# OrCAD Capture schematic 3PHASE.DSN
size A
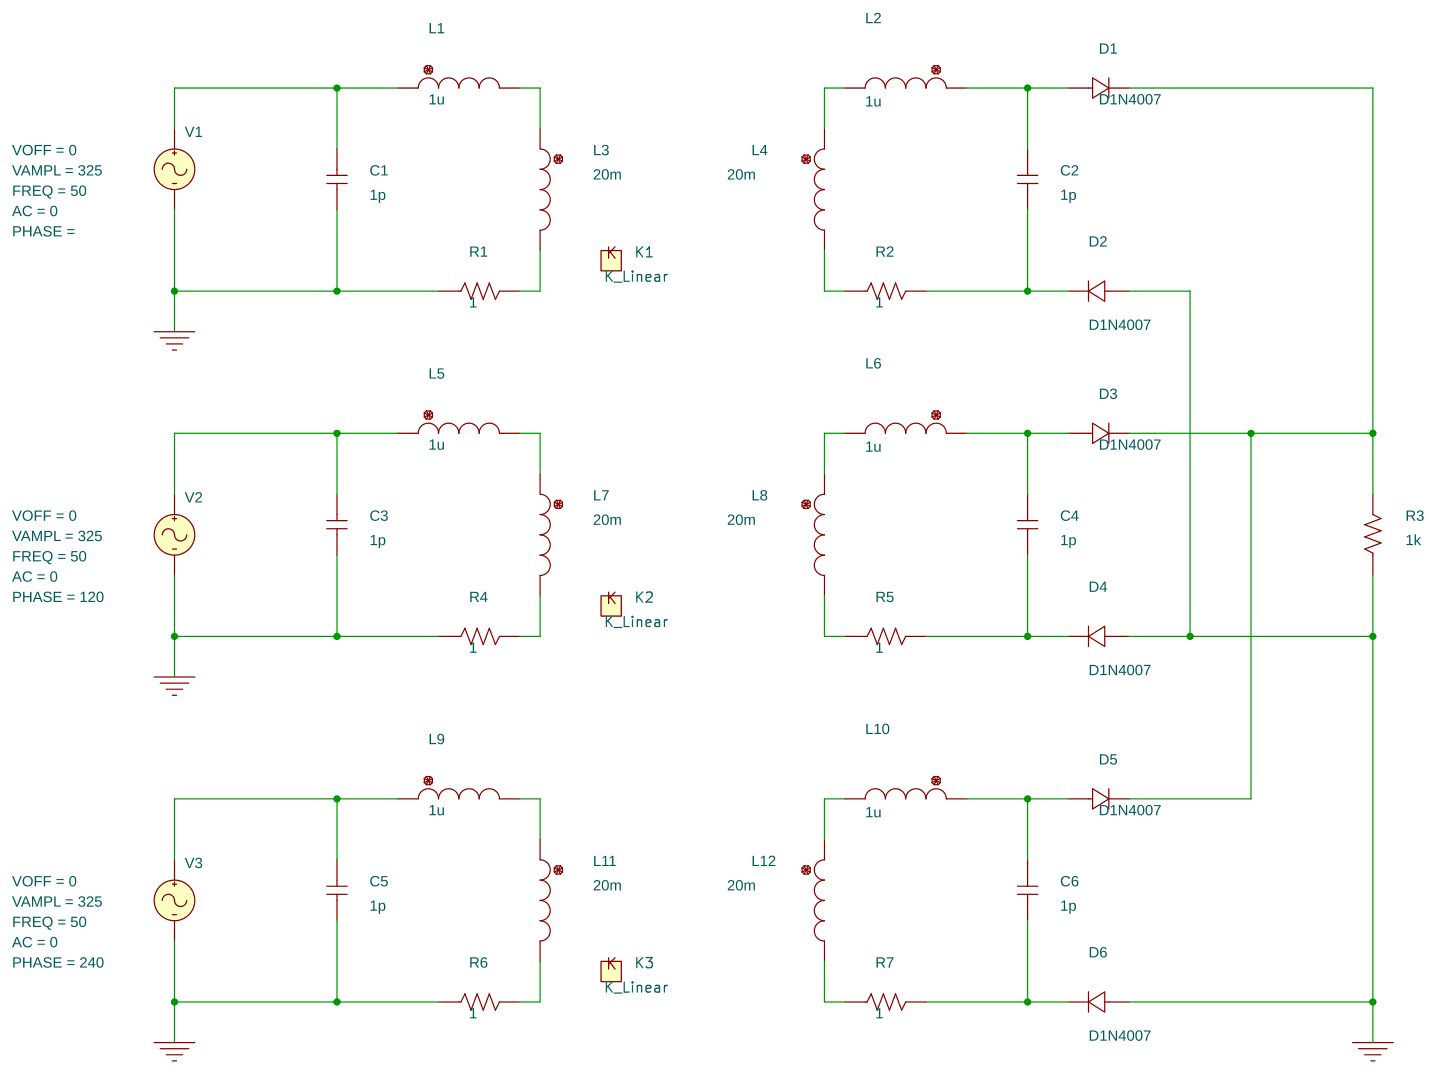
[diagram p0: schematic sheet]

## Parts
C1  1p  [RAD/CK05]
C2  1p  [RAD/CK05]
C3  1p  [RAD/CK05]
C4  1p  [RAD/CK05]
C5  1p  [RAD/CK05]
C6  1p  [RAD/CK05]
D1  D1N4007  [DO-41]
D2  D1N4007  [DO-41]
D3  D1N4007  [DO-41]
D4  D1N4007  [DO-41]
D5  D1N4007  [DO-41]
D6  D1N4007  [DO-41]
K1  K_Linear
K2  K_Linear
K3  K_Linear
L1  1u  [DISC/.350x.175/LS.200x.100/.034]
L2  1u  [DISC/.350x.175/LS.200x.100/.034]
L3  20m  [DISC/.350x.175/LS.200x.100/.034]
L4  20m  [DISC/.350x.175/LS.200x.100/.034]
L5  1u  [DISC/.350x.175/LS.200x.100/.034]
L6  1u  [DISC/.350x.175/LS.200x.100/.034]
L7  20m  [DISC/.350x.175/LS.200x.100/.034]
L8  20m  [DISC/.350x.175/LS.200x.100/.034]
L9  1u  [DISC/.350x.175/LS.200x.100/.034]
L10  1u  [DISC/.350x.175/LS.200x.100/.034]
L11  20m  [DISC/.350x.175/LS.200x.100/.034]
L12  20m  [DISC/.350x.175/LS.200x.100/.034]
R1  1  [AX/RC05]
R2  1  [AX/RC05]
R3  1k  [AX/RC05]
R4  1  [AX/RC05]
R5  1  [AX/RC05]
R6  1  [AX/RC05]
R7  1  [AX/RC05]
V1  VSIN
V2  VSIN
V3  VSIN

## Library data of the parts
C1-C6 = C
D1-D6 = D1N4007
K1 = K_Linear: L1: L3; L2: L4
K2 = K_Linear: L1: L7; L2: L8
K3 = K_Linear: L1: L11; L2: L12
L1-L12 = L
R1-R7 = R
V1 = VSIN: AC: 0; FREQ: 50; VAMPL: 325; VOFF: 0
V2 = VSIN: AC: 0; FREQ: 50; PHASE: 120; VAMPL: 325; VOFF: 0
V3 = VSIN: AC: 0; FREQ: 50; PHASE: 240; VAMPL: 325; VOFF: 0

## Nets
0: C1.1 C3.1 C5.1 D2.1 D4.1 D6.1 R1.1 R3.1 R4.1 R6.1 V1.2(-) V2.2(-) V3.2(-)
N00131: L1.2 L3.1
N00138: L3.2 R1.2
N00145: L2.2 L4.1
N00152: L4.2 R2.1
N00159: C2.2 D1.1 L2.1
N00163: C2.1 D2.2 R2.2
N00167: C1.2 L1.1 V1.1(+)
N00695: L5.2 L7.1
N00703: L7.2 R4.2
N00711: L6.2 L8.1
N00719: L8.2 R5.1
N00727: C4.2 D3.1 L6.1
N00731: C4.1 D4.2 R5.2
N00735: C3.2 L5.1 V2.1(+)
N01131: L9.2 L11.1
N01139: L11.2 R6.2
N01147: L10.2 L12.1
N01155: L12.2 R7.1
N01163: C6.2 D5.1 L10.1
N01167: C6.1 D6.2 R7.2
N01171: C5.2 L9.1 V3.1(+)
N01528: D1.2 D3.2 D5.2 R3.2
